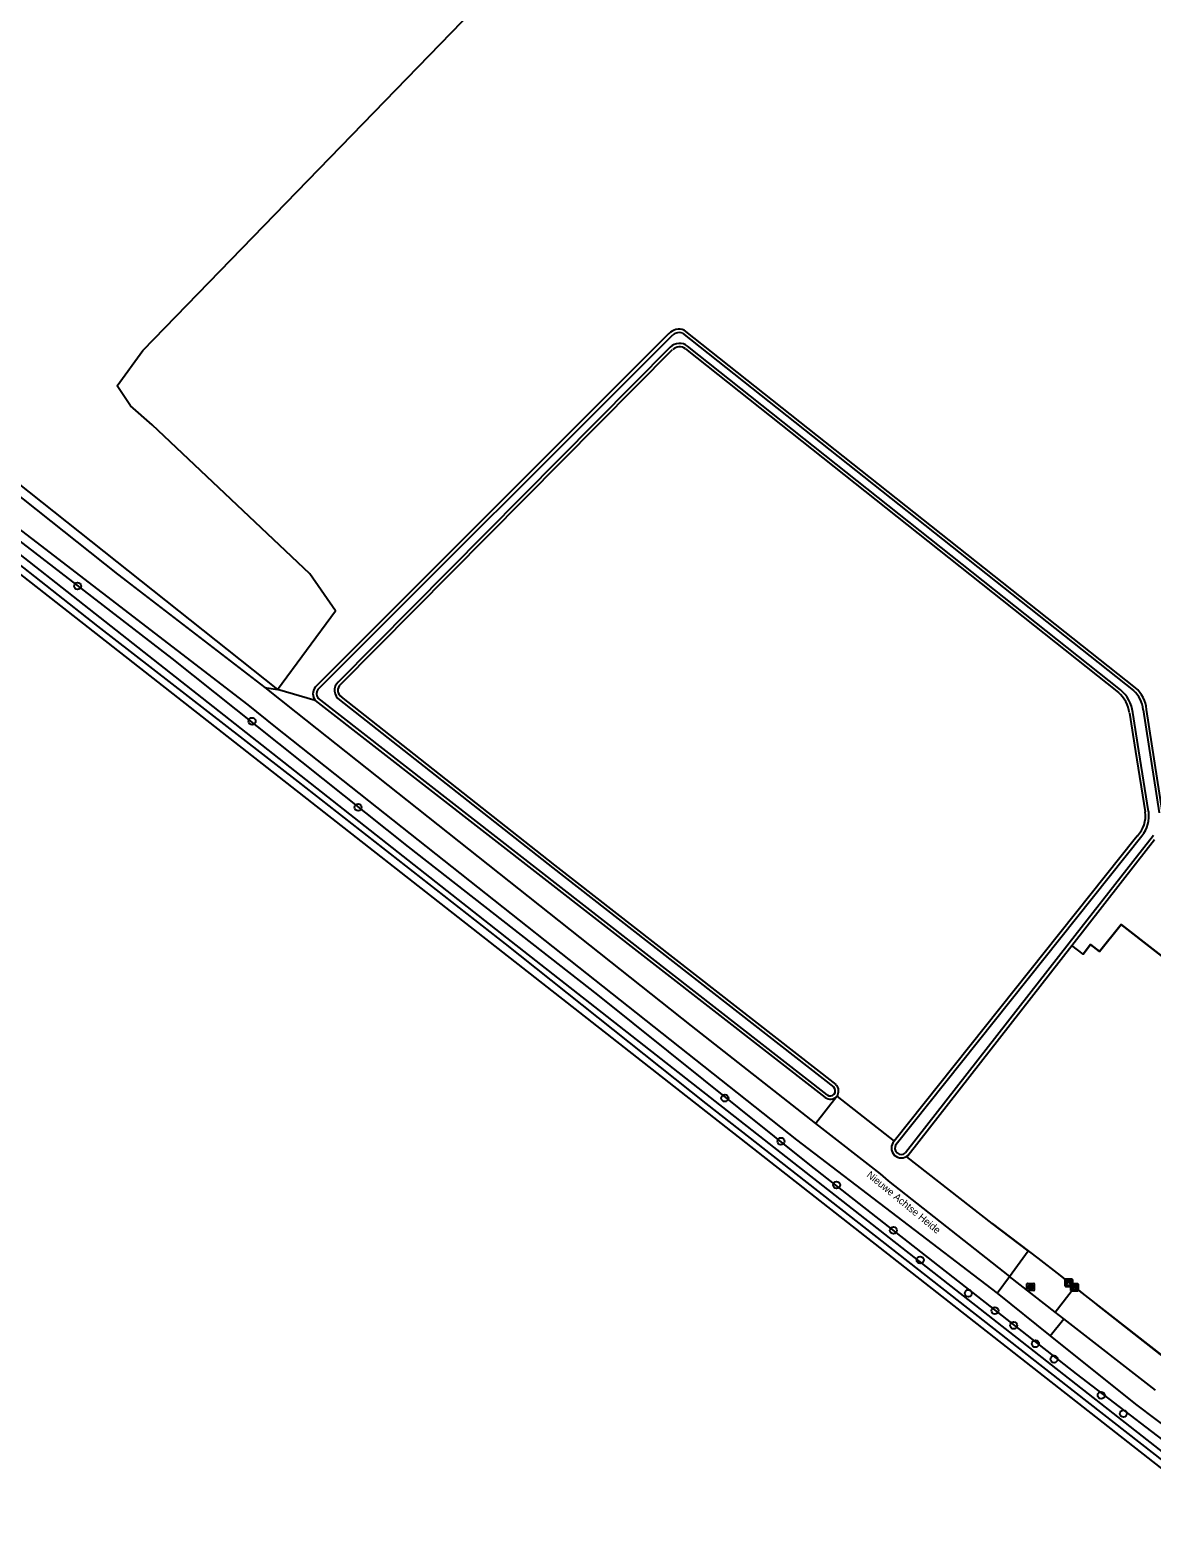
# Model space of a CAD drawing. Extents: x 155209 to 156823, y 385356 to 388482.
# Drawn here: x 155846 to 156002.3, y 387558.9 to 387769 of the extents above; entities that cross this region are included whole.
import ezdxf

# ---------------------------------------------------------------- set-up
doc = ezdxf.new("R2010")
doc.units = 0
for name, color, linetype in [('IMGEO_Boom', 7, 'Continuous'), ('IMGEO_Bouwland', 7, 'Continuous'), ('IMGEO_Duiker', 7, 'Continuous'), ('IMGEO_Erf', 7, 'Continuous'), ('IMGEO_Grasland_overig', 7, 'Continuous'), ('IMGEO_Groenvoorziening', 7, 'Continuous'), ('IMGEO_Kast', 7, 'Continuous'), ('IMGEO_Loofbos', 7, 'Continuous'), ('IMGEO_Muur', 7, 'Continuous'), ('IMGEO_Openbare_ruimte_label', 7, 'Continuous'), ('IMGEO_Rijbaan_lokaal_gesloten', 7, 'Continuous'), ('IMGEO_Rijbaan_lokaal_onverhard', 7, 'Continuous'), ('IMGEO_Rijbaan_lokaal_open', 7, 'Continuous'), ('IMGEO_Rioolput', 7, 'Continuous'), ('IMGEO_Sloot', 7, 'Continuous'), ('IMGEO_Voetpad_open', 7, 'Continuous'), ('IMGEO_Waterloop', 7, 'Continuous')]:
    doc.layers.add(name, color=color, linetype=linetype)

msp = doc.modelspace()

# ---------------------------------------------------------------- linework, layer by layer
at = {"layer": 'IMGEO_Boom'}
for centre in [(155852.58, 387691.54), (155876.9, 387672.71), (155891.66, 387660.72), (155942.77, 387620.19), (155950.59, 387614.19), (155958.34, 387608.09), (155966.26, 387601.76), (155969.99, 387597.64), (155976.7, 387593.01), (155980.4, 387590.59), (155983.01, 387588.52), (155986.05, 387585.96), (155988.65, 387583.82), (155995.21, 387578.79), (155998.3, 387576.22)]:
    msp.add_circle(centre, 0.489, dxfattribs=at)
at = {"layer": 'IMGEO_Bouwland'}
msp.add_lwpolyline([(156015.97, 387558.92), (156015.9, 387558.97), (155781.09, 387742.94)], dxfattribs=at)
at = {"layer": 'IMGEO_Duiker'}
msp.add_lwpolyline([(155958.37, 387620.45), (155966.36, 387614.2)], dxfattribs=at)
at = {"layer": 'IMGEO_Erf'}
msp.add_lwpolyline([(155968.32, 387612.24), (155991.14, 387641.47)], dxfattribs=at)
at = {"layer": 'IMGEO_Grasland_overig'}
for points in [[(155760.37, 387762.65), (155760.73, 387766.41), (155762.05, 387769.58), (155805.98, 387736.24), (155880.46, 387677.11)], [(155889.21, 387677.82), (155935.5, 387724.48)], [(155937.28, 387724.59), (155997.6, 387676.73)], [(155958.26, 387622.07), (155919.07, 387652.63), (155889.36, 387676.09)], [(155999.14, 387673.85), (156000, 387668.49), (156001.35, 387660.08)], [(156000.26, 387656.74), (156000, 387656.42), (155966.36, 387614.2)], [(155985.03, 387598.91), (155980.01, 387602.73), (155968.13, 387612), (155968.32, 387612.24)]]:
    msp.add_lwpolyline(points, dxfattribs=at)
for centre, radius, start, end in [((155936.46, 387723.49), 1.38, 53.2962, 133.6598), ((155889.95, 387677.01), 1.1, 132.8115, 237.254), ((155994.61, 387673.27), 4.57, 7.3643, 49.1467), ((155997.41, 387659.52), 3.98, 315.771, 8.0723), ((155957.44, 387621.2), 1.19, 320.9755, 46.7373), ((155967.37, 387613.25), 1.39, 136.9935, 312.9481)]:
    msp.add_arc(centre, radius, start, end, dxfattribs=at)
at = {"layer": 'IMGEO_Groenvoorziening'}
msp.add_lwpolyline([(156018.08, 387561.51), (156009, 387568.58), (155991.79, 387581.76), (155954.59, 387610.92), (155925.06, 387634.57), (155898.69, 387655.19), (155865.76, 387681.47), (155844.98, 387697.49), (155790.21, 387739.91), (155783.17, 387745.53), (155782.63, 387745.58), (155781.49, 387744.6), (155780.81, 387743.63), (155781.09, 387742.94)], dxfattribs=at)
at = {"layer": 'IMGEO_Kast'}
for p, q in [((155990.2, 387594.03), (155990.2, 387594.88)), ((155990.2, 387594.88), (155990.2, 387594.03)), ((155990.27, 387594.96), (155991.11, 387594.96)), ((155991.11, 387594.96), (155990.27, 387594.96)), ((155991, 387593.41), (155991, 387594.25)), ((155991, 387594.25), (155991, 387593.41)), ((155991.07, 387594.34), (155991.91, 387594.34)), ((155991.91, 387594.34), (155991.07, 387594.34)), ((155991.2, 387594.89), (155991.2, 387594.04)), ((155991.2, 387594.04), (155991.2, 387594.89)), ((155992, 387594.26), (155992, 387593.42)), ((155992, 387593.42), (155992, 387594.26)), ((155991.12, 387593.96), (155990.28, 387593.96)), ((155990.28, 387593.96), (155991.12, 387593.96)), ((155991.92, 387593.34), (155991.08, 387593.34)), ((155991.08, 387593.34), (155991.92, 387593.34))]:
    msp.add_line(p, q, dxfattribs=at)
for points in [[(155990.39, 387594.75), (155990.99, 387594.75), (155990.99, 387594.66), (155990.39, 387594.66), (155990.39, 387594.75)], [(155990.39, 387594.58), (155990.99, 387594.58), (155990.99, 387594.09), (155990.39, 387594.09), (155990.39, 387594.58)], [(155991.19, 387594.13), (155991.79, 387594.13), (155991.79, 387594.04), (155991.19, 387594.04), (155991.19, 387594.13)], [(155991.19, 387593.95), (155991.79, 387593.95), (155991.79, 387593.47), (155991.19, 387593.47), (155991.19, 387593.95)]]:
    msp.add_lwpolyline(points, dxfattribs=at)
for centre in [(155990.48, 387594.42), (155991.27, 387593.8)]:
    msp.add_circle(centre, 0.0377, dxfattribs=at)
for centre, start, end in [((155990.28, 387594.88), 92.4484, 184.2845), ((155990.28, 387594.88), 92.4484, 184.2845), ((155990.28, 387594.04), 182.4484, 274.2845), ((155990.28, 387594.04), 182.4484, 274.2845), ((155991.07, 387594.26), 92.4484, 184.2845), ((155991.07, 387594.26), 92.4484, 184.2845), ((155991.12, 387594.88), 2.4484, 94.2845), ((155991.12, 387594.88), 2.4484, 94.2845), ((155991.12, 387594.04), 272.4484, 4.2845), ((155991.12, 387594.04), 272.4484, 4.2845), ((155991.92, 387594.26), 2.4484, 94.2845), ((155991.92, 387594.26), 2.4484, 94.2845), ((155991.07, 387593.42), 182.4484, 274.2845), ((155991.07, 387593.42), 182.4484, 274.2845), ((155991.92, 387593.42), 272.4484, 4.2845), ((155991.92, 387593.42), 272.4484, 4.2845)]:
    msp.add_arc(centre, 0.0779, start, end, dxfattribs=at)
at = {"layer": 'IMGEO_Loofbos'}
for points in [[(155880.46, 387677.11), (155888.52, 387688.09), (155884.95, 387693.25), (155862.99, 387714.02), (155859.95, 387716.66), (155858.1, 387719.44), (155861.67, 387724.34), (155938.4, 387803.45), (155950.04, 387812.44), (155989.33, 387835.59), (155996.61, 387838.37)], [(155934.98, 387726.71), (155885.7, 387677.44)], [(156000, 387677.37), (155937.1, 387727.2)], [(155878.67, 387677.4), (155880.46, 387677.11)], [(155885.7, 387675.61), (155880.46, 387677.11)], [(155885.7, 387675.61), (155956.73, 387620.29)], [(156003.74, 387660.01), (156001.53, 387674.36)], [(155991.14, 387641.47), (156000, 387652.82), (156002.65, 387656.21)], [(156008.69, 387580.4), (156023.21, 387602.29), (156025.53, 387607.15), (156026.18, 387610.83), (156025.05, 387613.71), (156022.6, 387616.69), (156013.5, 387629.9), (156007.67, 387636.87), (155998, 387644.4), (155994.98, 387640.64), (155993.71, 387641.58), (155992.72, 387640.24), (155991.14, 387641.47)], [(155955.41, 387616.68), (155958.37, 387620.45)]]:
    msp.add_lwpolyline(points, dxfattribs=at)
for centre, radius, start, end in [((155936.39, 387725.41), 1.92, 68.3536, 137.4506), ((155886.8, 387676.52), 1.43, 140.1849, 219.8151), ((155996.96, 387673.92), 4.6, 5.4947, 48.5021), ((155957.47, 387621.22), 1.18, 231.855, 319.6702)]:
    msp.add_arc(centre, radius, start, end, dxfattribs=at)
at = {"layer": 'IMGEO_Muur'}
for points in [[(155992.72, 387640.24), (155993.71, 387641.58), (155994.98, 387640.64), (155998, 387644.4), (156007.67, 387636.87), (156013.5, 387629.9), (156022.6, 387616.69), (156025.05, 387613.71), (156026.18, 387610.83), (156025.53, 387607.15), (156023.21, 387602.29), (156008.69, 387580.4)], [(155980.01, 387602.73), (155986.4, 387597.87)], [(155989.48, 387595.46), (155992.71, 387592.93)], [(156008.69, 387580.4), (155994.6, 387591.45)]]:
    msp.add_lwpolyline(points, dxfattribs=at)
at = {"layer": 'IMGEO_Rijbaan_lokaal_gesloten'}
for points in [[(155988.1, 387587.08), (155990, 387589.45)], [(156002.78, 387579.5), (155990, 387589.45)], [(155988.1, 387587.08), (156000, 387577.57), (156008.49, 387571.12)]]:
    msp.add_lwpolyline(points, dxfattribs=at)
at = {"layer": 'IMGEO_Rijbaan_lokaal_onverhard'}
for points in [[(155761.75, 387762.78), (155763.39, 387767.02), (155776.38, 387757.04), (155816.85, 387726), (155858.15, 387693.18), (155878.67, 387677.4)], [(155779.18, 387749.74), (155783.72, 387746.22), (155795.66, 387736.94), (155876.29, 387674.98), (155880.15, 387671.9), (155952.77, 387614.37), (155980.71, 387593)], [(155878.67, 387677.4), (155883, 387673.97), (155938.06, 387630.28), (155955.41, 387616.68)], [(155955.41, 387616.68), (155964.39, 387609.63), (155965.55, 387608.69), (155982.42, 387595.34)]]:
    msp.add_lwpolyline(points, dxfattribs=at)
at = {"layer": 'IMGEO_Rijbaan_lokaal_open'}
for points in [[(155980.71, 387593), (155982.42, 387595.34)], [(155988.79, 387590.39), (155982.42, 387595.34)], [(155980.71, 387593), (155988.1, 387587.08)], [(155990, 387589.45), (155988.79, 387590.39)]]:
    msp.add_lwpolyline(points, dxfattribs=at)
at = {"layer": 'IMGEO_Rioolput'}
for p, q in [((155984.87, 387593.45), (155984.87, 387594.3)), ((155984.95, 387594.37), (155985.8, 387594.37)), ((155985.36, 387594.15), (155985.39, 387594.15)), ((155985.87, 387594.3), (155985.87, 387593.45)), ((155985.8, 387593.37), (155984.95, 387593.37)), ((155985.38, 387593.59), (155985.36, 387593.59))]:
    msp.add_line(p, q, dxfattribs=at)
for points in [[(155984.87, 387593.45), (155984.87, 387594.3)], [(155984.95, 387594.37), (155985.8, 387594.37)], [(155985.46, 387594.07), (155985.21, 387594.07), (155985.21, 387593.67)], [(155985.39, 387593.99), (155985.33, 387593.99), (155985.33, 387593.91)], [(155985.87, 387594.3), (155985.87, 387593.45)], [(155985.8, 387593.37), (155984.95, 387593.37)], [(155985.21, 387593.67), (155985.33, 387593.67), (155985.33, 387593.84), (155985.35, 387593.84)], [(155985.33, 387593.91), (155985.39, 387593.91)], [(155985.39, 387593.81), (155985.46, 387593.67), (155985.6, 387593.67), (155985.54, 387593.8)]]:
    msp.add_lwpolyline(points, dxfattribs=at)
for centre, radius, start, end in [((155984.95, 387594.3), 0.0765, 91.552, 178.448), ((155984.95, 387594.3), 0.0765, 91.552, 178.448), ((155985.39, 387593.9), 0.0964, 77.0061, 93.1865), ((155985.41, 387593.95), 0.0378, 276.6634, 79.6772), ((155985.46, 387593.96), 0.109, 350.3612, 89.416), ((155985.8, 387594.3), 0.0765, 1.552, 88.448), ((155985.8, 387594.3), 0.0765, 1.552, 88.448), ((155984.95, 387593.45), 0.0765, 181.552, 268.448), ((155984.95, 387593.45), 0.0765, 181.552, 268.448), ((155985.34, 387593.78), 0.0533, 26.0293, 88.6989), ((155985.37, 387594.1), 0.19, 274.7715, 282.9687), ((155985.46, 387593.96), 0.112, 277.5842, 350.9817), ((155985.44, 387593.75), 0.108, 29.5134, 73.7905), ((155985.8, 387593.45), 0.0765, 271.552, 358.448), ((155985.8, 387593.45), 0.0765, 271.552, 358.448)]:
    msp.add_arc(centre, radius, start, end, dxfattribs=at)
for centre, major_axis, ratio, start_param, end_param in [((155985.36, 387593.87), (-0.387, 0.002), 0.722429, 4.712389, 7.853982), ((155985.38, 387593.87), (-0.39, 0.002), 0.717154, 1.570796, 4.712389)]:
    msp.add_ellipse(centre, major_axis=major_axis, ratio=ratio, start_param=start_param, end_param=end_param, dxfattribs=at)
at = {"layer": 'IMGEO_Sloot'}
msp.add_lwpolyline([(155783.27, 387744.19), (155782.59, 387744.7), (155782.25, 387744.9), (155781.84, 387744.62), (155781.68, 387743.99), (155782.52, 387743.29), (155792.13, 387735.84), (155823.51, 387711.04), (155855.38, 387685.95), (155883.3, 387664.26), (155912.17, 387641.68), (155940.14, 387619.46), (155991.72, 387579.09), (156016.28, 387559.89), (156017.02, 387560.75), (156008.48, 387567.2), (155913.04, 387642.03), (155783.27, 387744.19)], dxfattribs=at)
at = {"layer": 'IMGEO_Voetpad_open'}
for points in [[(155982.42, 387595.34), (155985.03, 387598.91)], [(155985.03, 387598.91), (155986.4, 387597.87), (155989.48, 387595.46), (155991.51, 387593.86)], [(155988.79, 387590.39), (155991.51, 387593.86)], [(155991.51, 387593.86), (156005.46, 387582.93)]]:
    msp.add_lwpolyline(points, dxfattribs=at)
at = {"layer": 'IMGEO_Waterloop'}
for points in [[(155886.06, 387677.12), (155935.51, 387726.56)], [(155936.86, 387726.78), (155999.69, 387677)], [(155935.17, 387724.83), (155888.87, 387678.16)], [(155997.9, 387677.1), (155937.57, 387724.97)], [(155957.04, 387620.66), (155886.04, 387675.95)], [(155889.08, 387675.7), (155918.78, 387652.26), (155957.95, 387621.71)], [(156001.82, 387660.15), (156000.47, 387668.57), (155999.61, 387673.92)], [(156001.06, 387674.31), (156003.27, 387659.94)], [(155966.62, 387613.76), (156000.89, 387656.73)], [(156002.52, 387656.8), (155999.62, 387653.11), (155990.76, 387641.77), (155967.96, 387612.57)]]:
    msp.add_lwpolyline(points, dxfattribs=at)
for centre, radius, start, end in [((155936.39, 387725.42), 1.44, 70.8925, 127.592), ((155936.46, 387723.49), 1.86, 53.012, 133.9389), ((155889.95, 387677.01), 1.57, 133.2167, 236.3183), ((155886.8, 387676.52), 0.949, 141.3982, 217.0267), ((155994.6, 387673.26), 5.06, 7.4983, 49.2303), ((155996.96, 387673.93), 4.11, 5.2867, 48.3694), ((155997.41, 387659.52), 4.46, 321.2984, 8.1261), ((155957.47, 387621.2), 0.695, 231.4798, 46.521), ((155967.37, 387613.25), 0.908, 145.8711, 310.8829)]:
    msp.add_arc(centre, radius, start, end, dxfattribs=at)

# ---------------------------------------------------------------- texts
at = {"layer": 'IMGEO_Openbare_ruimte_label'}
msp.add_text('Nieuwe Achtse Heide', height=1, rotation=320.5614, dxfattribs=at).set_placement((155962.45, 387609.34))

doc.saveas('drawing.dxf')
